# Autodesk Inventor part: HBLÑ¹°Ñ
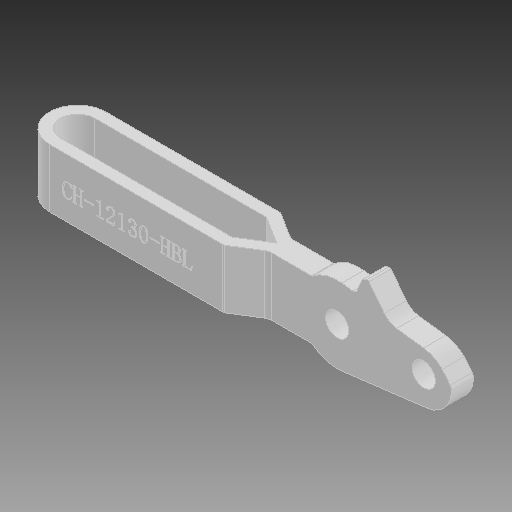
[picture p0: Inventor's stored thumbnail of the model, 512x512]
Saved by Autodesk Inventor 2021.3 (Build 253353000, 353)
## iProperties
Created: 2020-03
Part Number: HBLÑ¹°Ñ
Material: Ogólny
Document SubType Name: Modeling
Designer: Przemyslaw Krecisz
Density: 1 g/cm^3
Appearance: Domyślna
Author: Przemyslaw Krecisz
Revision Number: ÈÎºÎ
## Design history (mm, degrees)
feature "°ü¸²1"
node "Bryła1"
